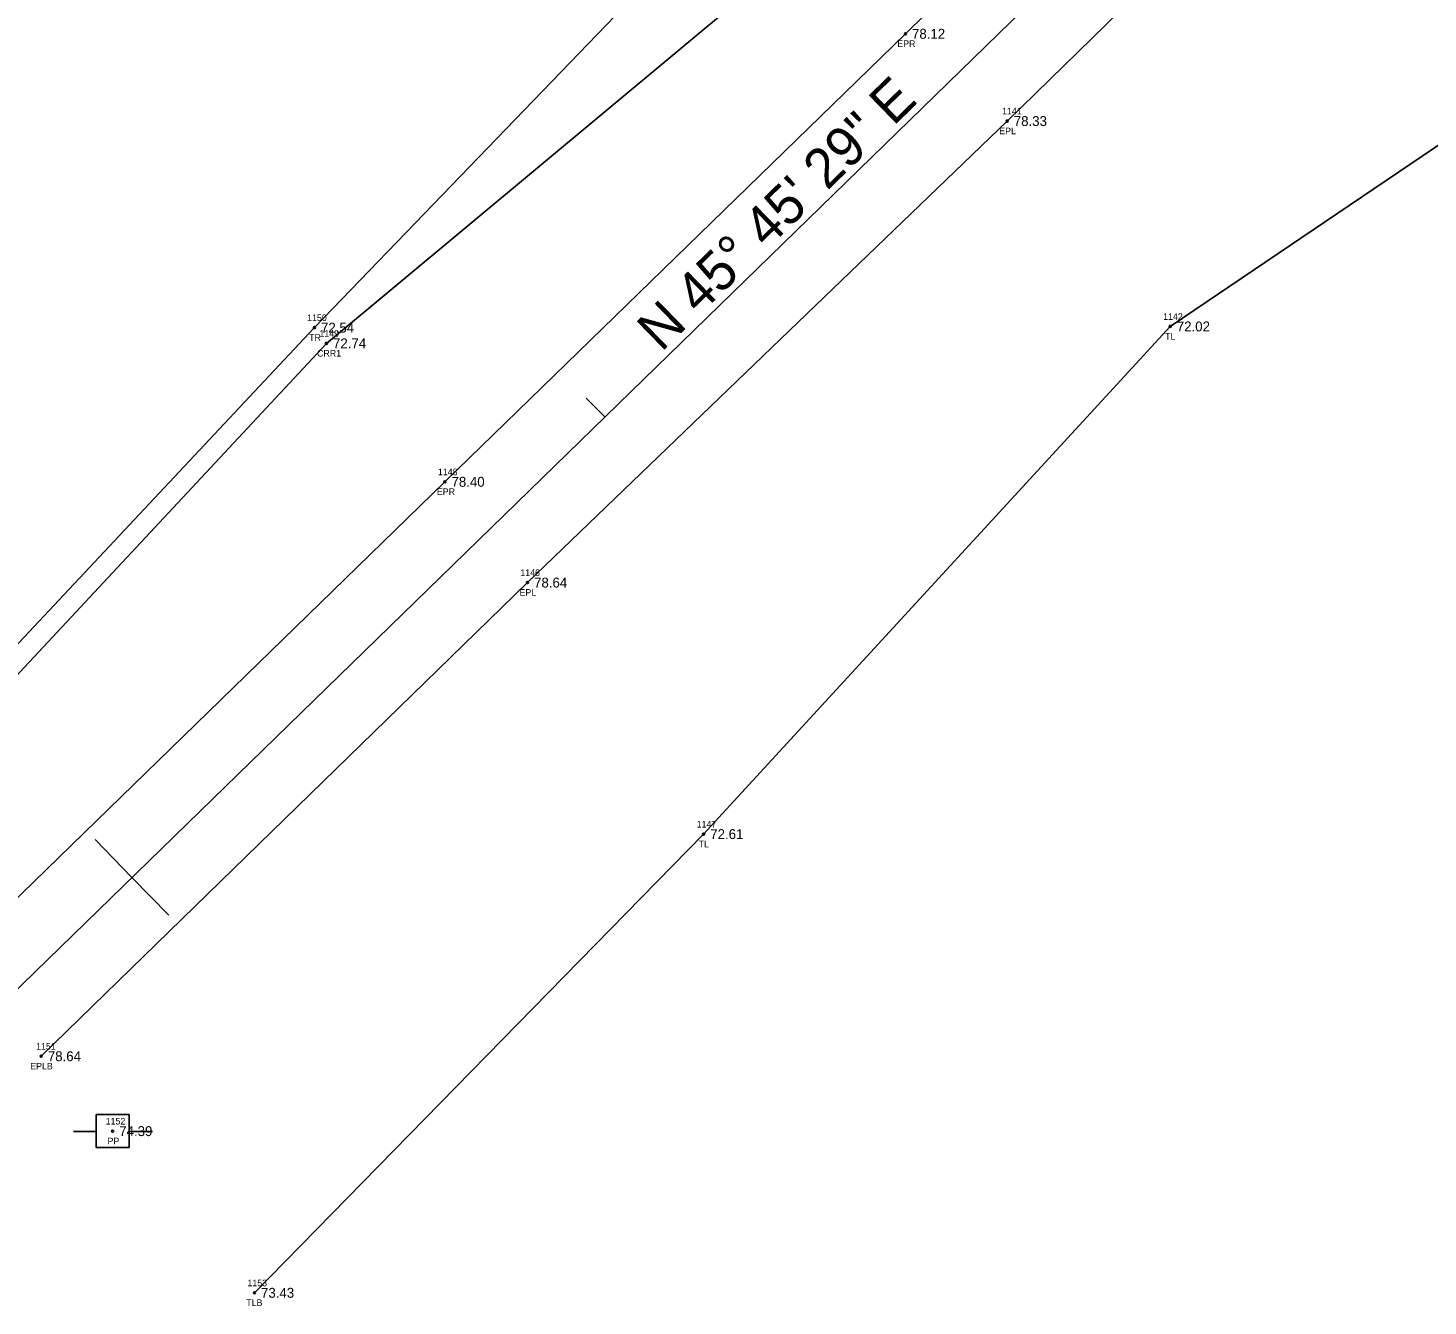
# Model space of a CAD drawing. Extents: x 2505249 to 2506333, y 912937 to 914171.
# Drawn here: x 2505368.6 to 2505580.7, y 913003.9 to 913197.6 of the extents above; entities that cross this region are included whole.
import ezdxf

# ---------------------------------------------------------------- set-up
doc = ezdxf.new("R2010")
doc.units = 0
for name, color, linetype in [('RD_EX_H2O', 7, 'Continuous'), ('RD_EX_H2O_txCode', 7, 'Continuous'), ('RD_EX_Road', 7, 'Continuous'), ('RD_EX_Road_txCode', 7, 'Continuous'), ('RD_EX_TX_H2O_ELEV', 7, 'Continuous'), ('RD_EX_TX_Road_ELEV', 7, 'Continuous'), ('RD_EX_TX_VEG_ELEV', 7, 'Continuous'), ('RD_EX_UT', 7, 'Continuous'), ('RD_EX_UT_txCode', 7, 'Continuous'), ('RD_EX_VEG', 7, 'Continuous'), ('RD_EX_VEG_txCode', 7, 'Continuous'), ('RD_HC_Cl', 7, 'Continuous'), ('RD_HC_Data', 7, 'Continuous'), ('RD_HC_Data_Tic', 7, 'Continuous'), ('RD_HC_Survey_ELEV', 7, 'Continuous'), ('RD_SMD_Locator', 7, 'Continuous')]:
    doc.layers.add(name, color=color, linetype=linetype)

msp = doc.modelspace()

# ---------------------------------------------------------------- linework, layer by layer
at = {"layer": 'RD_EX_H2O'}
msp.add_lwpolyline([(2505789.47, 913464.31), (2505758.18, 913486.1), (2505736.66, 913480.49), (2505719.32, 913463.86), (2505699.9, 913439.21), (2505669.03, 913402.75), (2505628.5, 913357.9), (2505593, 913316.39), (2505556.58, 913279.8), (2505487.72, 913211.38), (2505413.81, 913149.81), (2505341.31, 913072.1)], dxfattribs=at)
at = {"layer": 'RD_EX_Road'}
for points in [[(2505758.23, 913470.96), (2505754.11, 913462.85), (2505725.4, 913427.85), (2505690.77, 913387.11), (2505650.25, 913343.36), (2505607.72, 913300.12), (2505570.97, 913264.99), (2505501.53, 913196.72), (2505431.76, 913128.83), (2505356.25, 913055.37)], [(2505777.56, 913455.88), (2505770.31, 913449.85), (2505741, 913414.45), (2505705.55, 913374.27), (2505664.83, 913329.82), (2505624.02, 913288.23), (2505585.62, 913250.63), (2505516.95, 913183.5), (2505444.27, 913113.56), (2505370.6, 913041.78)]]:
    msp.add_lwpolyline(points, dxfattribs=at)
at = {"layer": 'RD_EX_UT'}
for p, q in [((2505383.91, 913032.94), (2505378.91, 913032.94)), ((2505378.91, 913032.94), (2505378.91, 913027.94)), ((2505383.91, 913027.94), (2505383.91, 913032.94)), ((2505375.48, 913030.38), (2505378.95, 913030.38)), ((2505383.84, 913030.38), (2505387.48, 913030.38)), ((2505378.91, 913027.94), (2505383.91, 913027.94))]:
    msp.add_line(p, q, dxfattribs=at)
at = {"layer": 'RD_EX_VEG'}
for points in [[(2506002.64, 913815.25), (2505883.7, 913669.64), (2505827.83, 913593.29), (2505814.43, 913589.15), (2505792.49, 913560.55), (2505725.64, 913468.24), (2505664.37, 913399.09), (2505478.33, 913221), (2505411.99, 913152.19), (2505339.13, 913074.53)], [(2505850.96, 913443.27), (2505787.55, 913373.63), (2505723.35, 913275.26), (2505541.65, 913152.37), (2505470.96, 913075.44), (2505402.9, 913005.93)]]:
    msp.add_lwpolyline(points, dxfattribs=at)
at = {"layer": 'RD_HC_Cl'}
msp.add_line((2505363.33, 913048.43), (2505609.42, 913288.1), dxfattribs=at)
at = {"layer": 'RD_HC_Data_Tic'}
for p, q in [((2505455.97, 913138.66), (2505453.18, 913141.52)), ((2505384.33, 913068.89), (2505378.75, 913074.62)), ((2505384.33, 913068.89), (2505389.91, 913063.16))]:
    msp.add_line(p, q, dxfattribs=at)
at = {"layer": 'RD_SMD_Locator'}
for centre in [(2505501.53, 913196.72), (2505516.95, 913183.5), (2505411.99, 913152.19), (2505541.65, 913152.37), (2505413.81, 913149.81), (2505431.76, 913128.83), (2505444.27, 913113.56), (2505470.96, 913075.44), (2505370.6, 913041.78), (2505381.42, 913030.43), (2505402.9, 913005.93)]:
    msp.add_circle(centre, 0.15, dxfattribs=at)

# ---------------------------------------------------------------- texts
at = {"layer": 'RD_EX_H2O_txCode'}
for s, p in [('1149', (2505412.75, 913150.81)), ('CRR1', (2505412.39, 913147.81))]:
    msp.add_text(s, height=1, dxfattribs=at).set_placement(p)
at = {"layer": 'RD_EX_Road_txCode'}
for s, p in [('EPR', (2505500.3, 913194.72)), ('1141', (2505516.17, 913184.5)), ('EPL', (2505515.75, 913181.5)), ('1148', (2505430.7, 913129.83)), ('EPR', (2505430.54, 913126.83)), ('1146', (2505443.18, 913114.56)), ('EPL', (2505443.06, 913111.56)), ('1151', (2505369.82, 913042.78)), ('EPLB', (2505368.93, 913039.78))]:
    msp.add_text(s, height=1, dxfattribs=at).set_placement(p)
at = {"layer": 'RD_EX_TX_H2O_ELEV'}
msp.add_text('72.74', height=1.5, dxfattribs=at).set_placement((2505414.81, 913149.06))
at = {"layer": 'RD_EX_TX_Road_ELEV'}
for s, p in [('78.12', (2505502.53, 913195.97)), ('78.33', (2505517.95, 913182.75)), ('78.40', (2505432.76, 913128.08)), ('78.64', (2505445.27, 913112.81)), ('78.64', (2505371.6, 913041.03))]:
    msp.add_text(s, height=1.5, dxfattribs=at).set_placement(p)
at = {"layer": 'RD_EX_TX_VEG_ELEV'}
for s, p in [('72.02', (2505542.65, 913151.62)), ('72.54', (2505412.99, 913151.44)), ('72.61', (2505471.96, 913074.69)), ('73.43', (2505403.9, 913005.18))]:
    msp.add_text(s, height=1.5, dxfattribs=at).set_placement(p)
at = {"layer": 'RD_EX_UT_txCode'}
for s, p in [('1152', (2505380.36, 913031.43)), ('PP', (2505380.64, 913028.43))]:
    msp.add_text(s, height=1, dxfattribs=at).set_placement(p)
at = {"layer": 'RD_EX_VEG_txCode'}
for s, p in [('1150', (2505410.88, 913153.19)), ('1142', (2505540.58, 913153.37)), ('TR', (2505411.19, 913150.19)), ('TL', (2505540.87, 913150.37)), ('1147', (2505469.9, 913076.44)), ('TL', (2505470.19, 913073.44)), ('1153', (2505401.84, 913006.93)), ('TLB', (2505401.66, 913003.93))]:
    msp.add_text(s, height=1, dxfattribs=at).set_placement(p)
at = {"layer": 'RD_HC_Data'}
msp.add_text('N 45%%d 45\' 29" E', height=6, rotation=44.2421, dxfattribs=at).set_placement((2505464.54, 913148.4))
at = {"layer": 'RD_HC_Survey_ELEV'}
msp.add_text('74.39', height=1.5, dxfattribs=at).set_placement((2505382.42, 913029.68))

doc.saveas('drawing.dxf')
